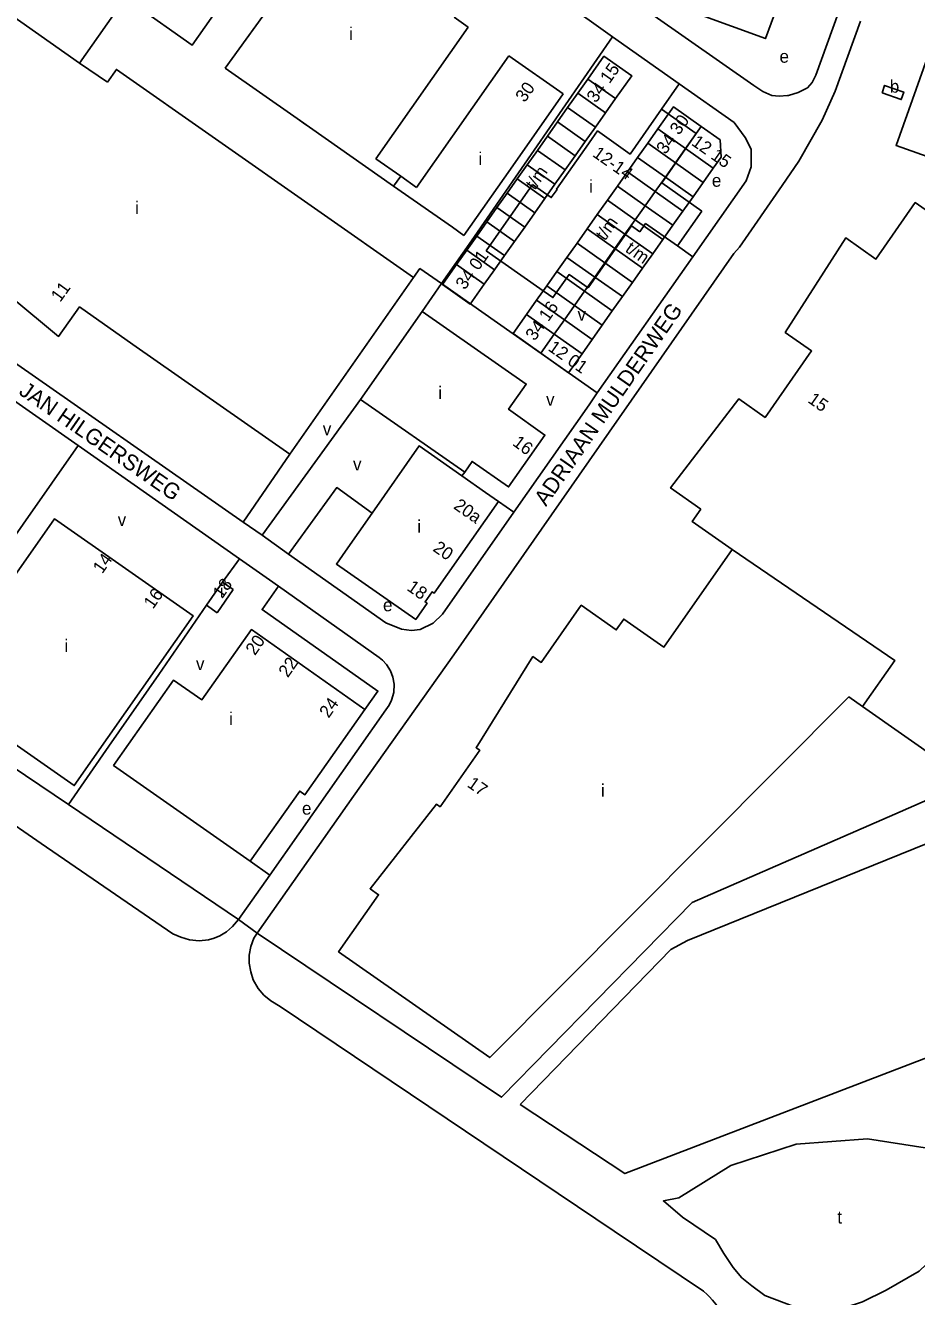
# Model space of a CAD drawing. Extents: x 154765 to 156627, y 383996 to 386132.
# Drawn here: x 155422.2 to 155703.2, y 384500 to 384900.8 of the extents above; entities that cross this region are included whole.
import ezdxf

# ---------------------------------------------------------------- set-up
doc = ezdxf.new("R2010")
doc.units = 0
for name, color, linetype in [('BLT_Basislijn', 7, 'Continuous'), ('BLT_Bebouwing', 7, 'Continuous'), ('BLT_Centroide', 7, 'Continuous'), ('BLT_Huisnummer', 7, 'Continuous'), ('BLT_Huisnummer_reeks', 7, 'Continuous'), ('BLT_Huisnummer_zonder_bebouwing', 7, 'Continuous'), ('BLT_Onderverdeling_panden', 7, 'Continuous'), ('BLT_Plantopo', 7, 'Continuous'), ('BLT_Straatnaam', 7, 'Continuous'), ('BLT_Vlakafsluiter', 7, 'Continuous')]:
    doc.layers.add(name, color=color, linetype=linetype)

msp = doc.modelspace()

# ---------------------------------------------------------------- linework, layer by layer
at = {"layer": 'BLT_Basislijn'}
for p, q in [((155498.87, 384973.86), (155439.29, 384888.96)), ((155680.83, 384911.21), (155671.48, 384885.12)), ((155607.31, 384897.29), (155562.92, 384832.94)), ((155628.38, 384882.41), (155607.31, 384897.29)), ((155670.3, 384882.89), (155671.48, 384885.12)), ((155622.82, 384874.46), (155628.38, 384882.41)), ((155651.95, 384881.89), (155654.77, 384879.98)), ((155654.77, 384879.98), (155657.57, 384878.78)), ((155662.89, 384878.78), (155665.89, 384879.68)), ((155665.89, 384879.68), (155668.8, 384881.19)), ((155668.8, 384881.19), (155670.3, 384882.89)), ((155657.57, 384878.78), (155659.88, 384878.58)), ((155659.88, 384878.58), (155662.5, 384878.76)), ((155662.5, 384878.76), (155662.89, 384878.78)), ((155627.79, 384831.29), (155632.65, 384827.88)), ((155553.44, 384819.41), (155547.35, 384810.66)), ((155553.44, 384819.41), (155602.55, 384785)), ((155490.88, 384744.23), (155400, 384807.65)), ((155400, 384795.58), (155438.84, 384768.34)), ((155527.93, 384782.9), (155496.87, 384740.05)), ((155384.1, 384690.1), (155438.84, 384768.34)), ((155438.84, 384768.34), (155489.69, 384732.68)), ((155505.6, 384765.6), (155490.88, 384744.23)), ((155560.73, 384760), (155559.87, 384758.76)), ((155571.35, 384750.72), (155576.24, 384747.3)), ((155489.69, 384732.68), (155484.37, 384725.28)), ((155479.3, 384717.99), (155464.27, 384696.13)), ((155384.1, 384690.1), (155435.77, 384655.16)), ((155448.58, 384673.58), (155435.77, 384655.16)), ((155400, 384661.46), (155427.23, 384642.88)), ((155435.77, 384655.16), (155489.41, 384618.88)), ((155493.14, 384637.26), (155499.29, 384632.92)), ((155607.86, 384520.66), (155502.6, 384591.47)), ((155636.05, 384501.69), (155607.86, 384520.66))]:
    msp.add_line(p, q, dxfattribs=at)
for points in [[(155607.31, 384897.29), (155600, 384902.45), (155498.87, 384973.86)], [(155620.48, 384903.87), (155622.3, 384908.85), (155655.58, 384896.67), (155660.96, 384911.36), (155627.69, 384923.55), (155629.83, 384929.4)], [(155620.48, 384903.87), (155651.95, 384881.89)], [(155685.56, 384902.17), (155677.57, 384880.07), (155673.46, 384870.93), (155666.12, 384858.04)], [(155632.65, 384827.88), (155649.46, 384851.83), (155651.06, 384856.23), (155651.06, 384861.77), (155649.22, 384865.46), (155645.7, 384870.18), (155628.38, 384882.41)], [(155647.35, 384830.88), (155660.8, 384850.31), (155666.12, 384858.04)], [(155553.44, 384819.41), (155562.92, 384832.94)], [(155579.42, 384734.02), (155600, 384763.51), (155645.55, 384828.96), (155647.35, 384830.88)], [(155602.55, 384785), (155632.65, 384827.88)], [(155544.63, 384821.3), (155546.64, 384824.17), (155553.44, 384819.41)], [(155576.24, 384747.3), (155600, 384781.22), (155602.55, 384785)], [(155531.51, 384747.04), (155520.39, 384755.1), (155505.2, 384734.15)], [(155553.74, 384715.17), (155576.24, 384747.3)], [(155496.87, 384740.05), (155490.88, 384744.23)], [(155505.2, 384734.15), (155496.87, 384740.05)], [(155489.69, 384732.68), (155499.24, 384725.97)], [(155553.74, 384715.17), (155550.76, 384712.29), (155546.68, 384710.36), (155543.94, 384710.07), (155540.76, 384710.42), (155535.9, 384712.42), (155505.2, 384734.15)], [(155557.3, 384702.31), (155579.42, 384734.02)], [(155529.3, 384685.14), (155533.37, 384690.93), (155496.87, 384716.61), (155502.06, 384723.98)], [(155499.24, 384725.97), (155502.06, 384723.98)], [(155502.06, 384723.98), (155533.78, 384701.54), (155534.79, 384700.7), (155536.06, 384699.31), (155537.37, 384697.27), (155538.07, 384695.35), (155538.45, 384693.06), (155538.36, 384690.51), (155537.67, 384688.09), (155536.92, 384686.49), (155535.91, 384684.98), (155499.29, 384632.92)], [(155696.4, 384652.06), (155860.39, 384724.09)], [(155578.26, 384560.55), (155625.71, 384609.45), (155630.96, 384612.32), (155823.58, 384690.32), (155852.37, 384714.19), (155862.96, 384718.92)], [(155862.96, 384718.92), (155868.89, 384707.02), (155878.23, 384686.96), (155883.19, 384671.24), (155878.85, 384660.35), (155864.72, 384648.14), (155860.33, 384643.55), (155826.95, 384621.49), (155611.26, 384538.75), (155578.26, 384560.55)], [(155557.3, 384702.31), (155525.66, 384657.81), (155495.3, 384614.54)], [(155464.27, 384696.13), (155448.58, 384673.58)], [(155696.4, 384652.06), (155632.42, 384624.25), (155572.33, 384562.82), (155495.3, 384614.54)], [(155427.23, 384642.88), (155468.67, 384614.33), (155471.23, 384613.36), (155473.99, 384612.53), (155477.02, 384612.16), (155479.91, 384612.45), (155481.76, 384613.02), (155483.48, 384613.79), (155485.58, 384615.03), (155487.51, 384616.7), (155489.41, 384618.88)], [(155499.29, 384632.92), (155489.41, 384618.88)], [(155495.3, 384614.54), (155494.26, 384613.05), (155493.28, 384610.38), (155492.8, 384607.69), (155492.8, 384605.11), (155493.29, 384602.37), (155494.08, 384599.9), (155495.64, 384597.15), (155497.41, 384595.05), (155499.65, 384593.25), (155502.6, 384591.47)], [(155628.26, 384531.13), (155644.65, 384541.35), (155665.3, 384548.05), (155687.79, 384549.74), (155705.92, 384546.85), (155721.5, 384550.01), (155728.41, 384544.89), (155734.71, 384537.35)], [(155734.71, 384537.35), (155704.01, 384507.98), (155693.62, 384502.02), (155686.13, 384498.37), (155680.99, 384496.61), (155675.34, 384495.78), (155669.38, 384495.69), (155664.51, 384496.83), (155655.33, 384500.35)], [(155628.26, 384531.13), (155623.38, 384530.15), (155629.39, 384525.04), (155639.78, 384518), (155642.4, 384513.61), (155645.38, 384509.16), (155648.17, 384505.88), (155651.24, 384503.38), (155655.33, 384500.35)], [(155636.05, 384501.69), (155637.22, 384500.6), (155637.8, 384500)], [(155637.8, 384500), (155638.88, 384498.82), (155639.9, 384497.59), (155640.85, 384496.3), (155641.74, 384494.98), (155642.55, 384493.61), (155643.3, 384492.2), (155643.35, 384492.1)]]:
    msp.add_lwpolyline(points, dxfattribs=at)
at = {"layer": 'BLT_Bebouwing'}
for p, q in [((155517.23, 384931.68), (155485.23, 384887.36)), ((155557.44, 384903.43), (155561.85, 384900.33)), ((155561.85, 384900.33), (155532.71, 384858.79)), ((155545.54, 384849.77), (155574.63, 384891.29)), ((155574.63, 384891.29), (155591.83, 384879.26)), ((155507.89, 384871.48), (155485.23, 384887.36)), ((155591.83, 384879.26), (155575.2, 384855.54)), ((155510.52, 384869.64), (155507.89, 384871.48)), ((155538.34, 384850.14), (155507.89, 384871.48)), ((155532.71, 384858.79), (155540.58, 384853.26)), ((155575.2, 384855.54), (155560.51, 384834.62)), ((155540.58, 384853.26), (155545.54, 384849.77)), ((155556.85, 384837.18), (155538.34, 384850.14)), ((155567.48, 384829.75), (155582.14, 384850.67)), ((155556.85, 384837.18), (155560.51, 384834.62)), ((155487.75, 384722.91), (155482.66, 384715.62)), ((155482.66, 384715.62), (155479.3, 384717.99)), ((155711.84, 384668.11), (155686.21, 384686.06))]:
    msp.add_line(p, q, dxfattribs=at)
for points in [[(155738.59, 384980.96), (155696.77, 384862.93), (155766.72, 384838.14), (155765.85, 384835.53), (155771.73, 384833.45), (155773.3, 384837.89), (155823.53, 384820.05), (155840.07, 384866.64), (155836.44, 384867.91), (155838.22, 384873.01), (155834.75, 384874.24), (155836.54, 384879.34), (155833.04, 384880.57), (155834.86, 384885.65), (155831.37, 384886.9), (155833.18, 384891.99), (155829.68, 384893.23), (155831.49, 384898.33), (155827.99, 384899.57), (155829.8, 384904.65)], [(155456.67, 384907.42), (155474.83, 384894.65), (155505.97, 384939.07)], [(155439.29, 384888.96), (155399.36, 384917.11)], [(155448.09, 384882.95), (155439.29, 384888.96)], [(155544.63, 384821.3), (155450.9, 384886.97), (155448.09, 384882.95)], [(155622.82, 384874.46), (155612.91, 384860.26), (155602.64, 384867.55), (155600, 384863.84), (155599.74, 384863.48), (155589.67, 384849.22), (155589.85, 384849.09), (155588.05, 384846.53), (155582.14, 384850.67)], [(155635.51, 384842.28), (155622.85, 384851.17), (155633.76, 384866.8), (155622.82, 384874.46)], [(155858.53, 384730.34), (155869.31, 384745.72), (155846.14, 384761.95), (155843.27, 384757.84), (155797.17, 384790.14), (155791.89, 384782.58), (155702.83, 384844.99), (155690.4, 384827.18), (155680.89, 384833.83), (155661.81, 384804.02), (155670.12, 384798.2), (155655.45, 384777.25), (155647.14, 384783.07), (155625.66, 384754.98), (155635.16, 384748.3)], [(155400, 384839.69), (155408.09, 384834.06), (155403.15, 384827.27), (155432.7, 384802.77), (155439.33, 384812.06), (155456.12, 384800.23), (155505.6, 384765.6)], [(155627.79, 384831.29), (155635.51, 384842.28)], [(155599.63, 384818.12), (155613.3, 384837.65), (155615.95, 384835.72)], [(155615.95, 384835.72), (155617.77, 384838.33), (155627.79, 384831.29)], [(155567.48, 384829.75), (155584.45, 384817.91), (155588.54, 384815.04), (155593.65, 384822.25), (155599.63, 384818.12)], [(155505.6, 384765.6), (155544.63, 384821.3)], [(155527.93, 384782.9), (155547.35, 384810.66)], [(155547.35, 384810.66), (155580.15, 384787.72), (155574.56, 384779.78), (155586.02, 384771.68), (155574.57, 384755.33), (155563.08, 384763.36), (155560.73, 384760)], [(155560.73, 384760), (155527.93, 384782.9)], [(155559.87, 384758.76), (155546.36, 384768.22), (155531.51, 384747.04)], [(155571.35, 384750.72), (155567.25, 384753.59), (155559.87, 384758.76)], [(155531.51, 384747.04), (155523.13, 384735.1), (155520.27, 384731), (155545.28, 384713.51), (155548.86, 384718.64), (155548.26, 384719.06), (155550.46, 384722.2), (155551.09, 384721.76), (155571.35, 384750.72)], [(155635.16, 384748.3), (155632.45, 384744.43), (155645.1, 384735.56)], [(155400, 384687.47), (155437.63, 384661.15), (155475.14, 384714.65), (155431.43, 384745.29), (155400, 384700.44)], [(155686.21, 384686.06), (155681.88, 384689.1), (155568.62, 384575.34), (155520.96, 384608.73), (155533.57, 384626.72), (155530.92, 384628.57), (155551.84, 384655.25), (155552.99, 384654.45), (155565.48, 384672.29), (155564.32, 384673.06), (155582.24, 384701.82), (155584.88, 384699.96), (155597.48, 384717.98), (155608.53, 384710.22), (155610.91, 384713.64), (155623.55, 384704.78), (155645.1, 384735.56)], [(155484.37, 384725.28), (155479.3, 384717.99)], [(155487.75, 384722.91), (155484.37, 384725.28)], [(155529.3, 384685.14), (155493.5, 384710.32), (155477.86, 384688.17), (155468.95, 384694.37), (155450.04, 384667.5), (155493.14, 384637.26)], [(155493.14, 384637.26), (155508.71, 384659.37), (155510.35, 384658.22), (155529.3, 384685.14)]]:
    msp.add_lwpolyline(points, dxfattribs=at)
msp.add_lwpolyline([(155692.36, 384879.59), (155693.16, 384881.93), (155699.2, 384879.8), (155698.38, 384877.48)], close=True, dxfattribs=at)
at = {"layer": 'BLT_Onderverdeling_panden'}
msp.add_line((155540.58, 384853.26), (155538.34, 384850.14), dxfattribs=at)
msp.add_lwpolyline([(155686.21, 384686.06), (155696.32, 384700.62), (155645.1, 384735.56)], dxfattribs=at)
at = {"layer": 'BLT_Plantopo'}
for p, q in [((155596.39, 384879.43), (155599.57, 384883.93)), ((155599.57, 384883.93), (155608.31, 384877.75)), ((155596.39, 384879.43), (155593.2, 384874.93)), ((155605.12, 384873.25), (155596.39, 384879.43)), ((155608.31, 384877.75), (155605.12, 384873.25)), ((155590.02, 384870.43), (155593.2, 384874.93)), ((155593.2, 384874.93), (155601.94, 384868.75)), ((155601.94, 384868.75), (155605.12, 384873.25)), ((155590.02, 384870.43), (155586.83, 384865.93)), ((155598.76, 384864.25), (155590.02, 384870.43)), ((155601.94, 384868.75), (155598.76, 384864.25)), ((155618.46, 384863.69), (155621.64, 384868.19)), ((155621.64, 384868.19), (155630.38, 384862.01)), ((155630.38, 384862.01), (155635.29, 384868.94)), ((155583.65, 384861.43), (155586.83, 384865.93)), ((155586.83, 384865.93), (155595.57, 384859.75)), ((155595.57, 384859.75), (155598.76, 384864.25)), ((155618.46, 384863.69), (155615.27, 384859.19)), ((155627.2, 384857.5), (155618.46, 384863.69)), ((155583.65, 384861.43), (155580.46, 384856.93)), ((155592.39, 384855.25), (155583.65, 384861.43)), ((155595.57, 384859.75), (155592.39, 384855.25)), ((155612.09, 384854.69), (155615.27, 384859.19)), ((155615.27, 384859.19), (155624.01, 384853)), ((155630.38, 384862.01), (155627.2, 384857.5)), ((155639.12, 384855.82), (155630.38, 384862.01)), ((155577.28, 384852.43), (155580.46, 384856.93)), ((155580.46, 384856.93), (155589.2, 384850.75)), ((155589.2, 384850.75), (155592.39, 384855.25)), ((155624.01, 384853), (155627.2, 384857.5)), ((155627.2, 384857.5), (155635.94, 384851.32)), ((155635.94, 384851.32), (155639.12, 384855.82)), ((155577.28, 384852.43), (155574.1, 384847.93)), ((155586.02, 384846.25), (155577.28, 384852.43)), ((155612.09, 384854.69), (155608.91, 384850.19)), ((155620.83, 384848.5), (155612.09, 384854.69)), ((155624.01, 384853), (155620.83, 384848.5)), ((155632.75, 384846.82), (155624.01, 384853)), ((155632.75, 384846.82), (155635.94, 384851.32)), ((155570.91, 384843.43), (155574.1, 384847.93)), ((155574.1, 384847.93), (155582.84, 384841.75)), ((155589.2, 384850.75), (155586.02, 384846.25)), ((155605.72, 384845.69), (155608.88, 384850.15)), ((155608.88, 384850.15), (155617.64, 384844)), ((155617.64, 384844), (155620.83, 384848.5)), ((155620.83, 384848.5), (155629.57, 384842.32)), ((155570.91, 384843.43), (155567.73, 384838.93)), ((155579.65, 384837.25), (155570.91, 384843.43)), ((155582.84, 384841.75), (155586.02, 384846.25)), ((155605.72, 384845.69), (155602.54, 384841.19)), ((155614.46, 384839.5), (155605.72, 384845.69)), ((155617.64, 384844), (155614.46, 384839.5)), ((155626.38, 384837.82), (155617.64, 384844)), ((155629.57, 384842.32), (155632.75, 384846.82)), ((155582.84, 384841.75), (155579.65, 384837.25)), ((155599.35, 384836.69), (155602.54, 384841.19)), ((155602.54, 384841.19), (155611.28, 384835)), ((155611.28, 384835), (155614.46, 384839.5)), ((155614.46, 384839.5), (155623.2, 384833.32)), ((155626.38, 384837.82), (155629.57, 384842.32)), ((155564.54, 384834.43), (155567.73, 384838.93)), ((155567.73, 384838.93), (155576.47, 384832.75)), ((155576.47, 384832.75), (155579.65, 384837.25)), ((155599.35, 384836.69), (155596.17, 384832.19)), ((155608.09, 384830.5), (155599.35, 384836.69)), ((155611.28, 384835), (155608.09, 384830.5)), ((155620.02, 384828.82), (155611.28, 384835)), ((155623.2, 384833.32), (155626.38, 384837.82)), ((155564.54, 384834.43), (155561.36, 384829.93)), ((155573.28, 384828.25), (155564.54, 384834.43)), ((155576.47, 384832.75), (155573.28, 384828.25)), ((155592.98, 384827.69), (155596.17, 384832.19)), ((155596.17, 384832.19), (155604.91, 384826)), ((155620.02, 384828.82), (155623.2, 384833.32)), ((155558.18, 384825.43), (155561.36, 384829.93)), ((155561.36, 384829.93), (155570.1, 384823.75)), ((155570.1, 384823.75), (155573.28, 384828.25)), ((155592.98, 384827.69), (155589.8, 384823.19)), ((155601.72, 384821.5), (155592.98, 384827.69)), ((155604.91, 384826), (155608.09, 384830.5)), ((155608.09, 384830.5), (155616.83, 384824.32)), ((155616.83, 384824.32), (155620.02, 384828.82)), ((155566.92, 384819.25), (155558.18, 384825.43)), ((155570.1, 384823.75), (155566.92, 384819.25)), ((155586.62, 384818.69), (155589.8, 384823.19)), ((155589.8, 384823.19), (155598.54, 384817)), ((155604.91, 384826), (155601.72, 384821.5)), ((155613.65, 384819.82), (155604.91, 384826)), ((155613.65, 384819.82), (155616.83, 384824.32)), ((155598.54, 384817), (155601.72, 384821.5)), ((155601.72, 384821.5), (155610.46, 384815.32)), ((155610.46, 384815.32), (155613.65, 384819.82)), ((155586.62, 384818.69), (155583.43, 384814.19)), ((155595.36, 384812.5), (155586.62, 384818.69)), ((155598.54, 384817), (155595.36, 384812.5)), ((155607.28, 384810.82), (155598.54, 384817)), ((155607.28, 384810.82), (155610.46, 384815.32)), ((155580.25, 384809.69), (155583.43, 384814.19)), ((155583.43, 384814.19), (155592.17, 384808)), ((155592.17, 384808), (155595.36, 384812.5)), ((155595.36, 384812.5), (155604.1, 384806.32)), ((155588.99, 384803.5), (155580.25, 384809.69)), ((155592.17, 384808), (155588.99, 384803.5)), ((155600.91, 384801.82), (155592.17, 384808)), ((155604.1, 384806.32), (155607.28, 384810.82)), ((155584.71, 384797.46), (155588.99, 384803.5)), ((155588.99, 384803.5), (155597.73, 384797.32)), ((155600.91, 384801.82), (155604.1, 384806.32)), ((155597.73, 384797.32), (155600.91, 384801.82))]:
    msp.add_line(p, q, dxfattribs=at)
for points in [[(155599.57, 384883.93), (155604.66, 384891.13), (155613.4, 384884.95), (155608.31, 384877.75)], [(155621.64, 384868.19), (155626.55, 384875.12), (155635.29, 384868.94)], [(155635.29, 384868.94), (155641.24, 384864.72), (155641.57, 384859.29), (155639.12, 384855.82)], [(155566.92, 384819.25), (155562.48, 384812.98), (155553.74, 384819.16), (155558.18, 384825.43)], [(155584.71, 384797.46), (155575.98, 384803.65), (155580.25, 384809.69)], [(155597.73, 384797.32), (155593.45, 384791.28), (155584.71, 384797.46)]]:
    msp.add_lwpolyline(points, dxfattribs=at)
at = {"layer": 'BLT_Vlakafsluiter'}
msp.add_line((155489.41, 384618.88), (155495.3, 384614.54), dxfattribs=at)

# ---------------------------------------------------------------- texts
at = {"layer": 'BLT_Centroide'}
for s, p in [('i', (155524.3, 384896.27)), ('e', (155660.01, 384889.08)), ('b', (155694.79, 384879.63)), ('i', (155565.08, 384856.84)), ('i', (155599.99, 384848.13)), ('e', (155638.67, 384849.97)), ('i', (155456.82, 384841.34)), ('v', (155596.31, 384807.74)), ('i', (155552.41, 384783)), ('v', (155586.4, 384780.94)), ('v', (155516, 384771.61)), ('v', (155525.53, 384760.51)), ('v', (155451.33, 384743)), ('i', (155545.81, 384740.84)), ('i', (155483.53, 384720.47)), ('e', (155534.99, 384716.09)), ('i', (155434.52, 384703.22)), ('v', (155476.01, 384697.55)), ('i', (155486.44, 384680.25)), ('i', (155603.71, 384657.58)), ('e', (155509.43, 384651.96)), ('t', (155678.23, 384523.01))]:
    msp.add_text(s, height=4, dxfattribs=at).set_placement(p)
at = {"layer": 'BLT_Huisnummer'}
for s, rotation, p in [('30', 54.9659, (155579.67, 384876.32)), ('15', 325.0024, (155668.67, 384782.15)), ('16', 323.3263, (155575.57, 384768.66)), ('18', 54.9588, (155484.24, 384719.81)), ('17', 325.0024, (155561.25, 384660.95))]:
    msp.add_text(s, height=4, rotation=rotation, dxfattribs=at).set_placement(p)
at = {"layer": 'BLT_Huisnummer_reeks'}
for s, rotation, p in [('12-14', 324.9255, (155600.78, 384859.74)), ('11', 54.029, (155433.18, 384813.35)), ('20a', 325.0352, (155556.95, 384748.69)), ('20', 325.0352, (155550.44, 384735.32)), ('14', 54.9767, (155446.44, 384727.68)), ('16', 54.9767, (155462.46, 384716.58)), ('18', 325.0352, (155542.24, 384722.93)), ('20', 55.1781, (155494.61, 384701.93)), ('22', 55.1781, (155504.97, 384694.95)), ('24', 55.1781, (155517.85, 384682.19))]:
    msp.add_text(s, height=4, rotation=rotation, dxfattribs=at).set_placement(p)
at = {"layer": 'BLT_Huisnummer_zonder_bebouwing'}
for s, rotation, p in [('34 15', 54.9659, (155602.12, 384876.17)), ('34 30', 54.9659, (155624.08, 384859.95)), ('12 15', 324.9659, (155631.97, 384863.31)), ('t/m', 54.9659, (155582.84, 384848.66)), ('t/m', 54.9659, (155604.97, 384832.69)), ('t/m', 324.9659, (155611.09, 384829.71)), ('34 01', 54.9659, (155560.8, 384817.23)), ('34 16', 54.9659, (155582.83, 384801.12)), ('12 01', 324.9659, (155586.75, 384798.53))]:
    msp.add_text(s, height=4, rotation=rotation, dxfattribs=at).set_placement(p)
at = {"layer": 'BLT_Straatnaam'}
for s, rotation, p in [('ADRIAAN MULDERWEG', 55.164, (155586.37, 384748.94)), ('JAN HILGERSWEG', 325.2991, (155419.84, 384784.71))]:
    msp.add_text(s, height=5, rotation=rotation, dxfattribs=at).set_placement(p)

doc.saveas('drawing.dxf')
